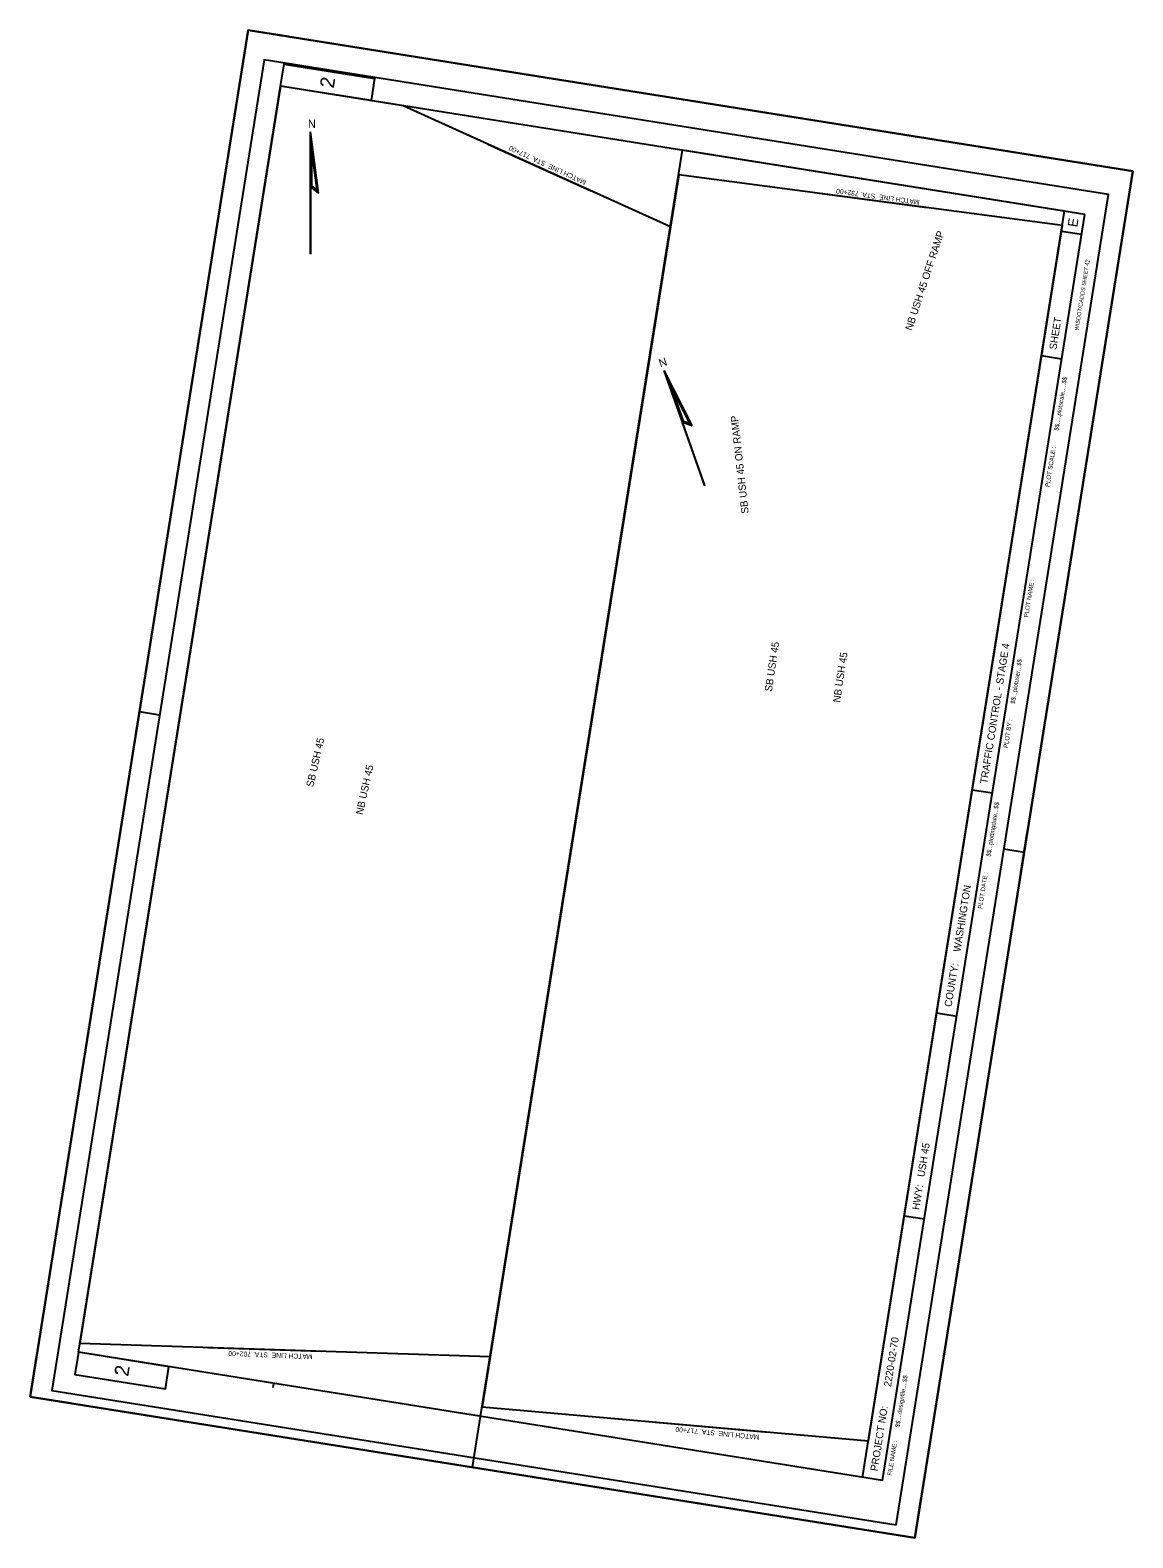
# Model space of a CAD drawing. Extents: x 354860 to 356215, y 192152 to 194004.
import ezdxf

# ---------------------------------------------------------------- set-up
doc = ezdxf.new("R2010")
doc.units = 0
for name, color, linetype in [('Default', 7, 'Continuous'), ('P_ALI_200_Equation', 7, 'Continuous'), ('P_ALI_200_PIData', 7, 'Continuous'), ('P_ALI_200_Sta', 7, 'Continuous'), ('P_ALI_20_PIData', 7, 'Continuous'), ('P_ALI_20_Tic', 7, 'Continuous'), ('P_ALI_50_Equation', 7, 'Continuous'), ('P_ALI_50_PIData', 7, 'Continuous'), ('P_ALI_50_Sta', 7, 'Continuous')]:
    doc.layers.add(name, color=color, linetype=linetype)

msp = doc.modelspace()

# ---------------------------------------------------------------- linework, layer by layer
at = {"layer": 'Default'}
for points in [[(354921.6, 192391.3), (355425.3, 192375.2), (355646.7, 193762.9), (355318.5, 193911.5), (355167.9, 193935.5)], [(354921.6, 192391.3), (355425.3, 192375.2), (355646.7, 193762.9), (355318.5, 193911.5), (355167.9, 193935.5)], [(354921.6, 192391.3), (355425.3, 192375.2), (355646.7, 193762.9), (355318.5, 193911.5), (355167.9, 193935.5)], [(355415.4, 192313.1), (355889.8, 192271.4), (356128, 193764.6), (355656.9, 193826.8)], [(355415.4, 192313.1), (355889.8, 192271.4), (356128, 193764.6), (355656.9, 193826.8)], [(355415.4, 192313.1), (355889.8, 192271.4), (356128, 193764.6), (355656.9, 193826.8)]]:
    msp.add_lwpolyline(points, close=True, dxfattribs=at)
at = {"layer": 'P_ALI_200_Equation'}
for points in [[(355946.7, 192152.3), (356214.5, 193831.1), (355128.3, 194004.4), (354860.4, 192325.6)], [(355923.9, 192168.1), (356184.6, 193802.4), (355147.7, 193967.9), (354887, 192333.5)]]:
    msp.add_lwpolyline(points, close=True, dxfattribs=at)
at = {"layer": 'P_ALI_200_PIData'}
for p, q in [((355120.4, 193955), (355128.3, 194004.4)), ((355177.6, 193996.5), (355128.3, 194004.4)), ((354919.8, 192380.2), (355167.9, 193935.5)), ((356155.4, 193778), (355167.9, 193935.5)), ((355413.5, 192301.4), (355661.7, 193856.8)), ((356214.5, 193831.1), (356165.1, 193839)), ((356206.6, 193781.7), (356214.5, 193831.1)), ((355882.6, 192226.6), (356130.7, 193781.9)), ((355907.3, 192222.7), (356155.4, 193778)), ((356151.5, 193753.3), (356126.8, 193757.2)), ((356127.1, 193600.2), (356102.4, 193604.2)), ((354990.8, 193142.8), (354998.7, 193192.1)), ((354994.7, 193167.5), (355019.4, 193163.5)), ((356042, 193067), (356017.3, 193070.9)), ((356077.1, 192969.5), (356084.9, 193018.8)), ((356081, 192994.2), (356056.3, 192998.1)), ((355998.3, 192792.9), (355973.6, 192796.9)), ((355958.5, 192543.6), (355933.8, 192547.5)), ((354860.4, 192325.6), (354868.3, 192375)), ((355907.3, 192222.7), (354919.8, 192380.2)), ((355159.3, 192342), (355158.5, 192337.1)), ((355419.4, 192338.5), (355419.4, 192338.5)), ((354909.8, 192317.7), (354860.4, 192325.6)), ((355403.6, 192239), (355413.5, 192301.4)), ((355428.3, 192235), (355378.9, 192242.9)), ((355946.7, 192152.3), (355954.6, 192201.7)), ((355946.7, 192152.3), (355897.3, 192160.2))]:
    msp.add_line(p, q, dxfattribs=at)
for points in [[(355167.9, 193935.5), (355172.2, 193962.7), (355283.3, 193945), (355279, 193917.8)], [(354919.8, 192380.2), (354915.4, 192353), (355026.5, 192335.3), (355030.9, 192362.5)]]:
    msp.add_lwpolyline(points, close=True, dxfattribs=at)
at = {"layer": 'P_ALI_200_Sta'}
msp.add_lwpolyline([(354860.4, 192325.6), (355128.3, 194004.4), (356214.5, 193831.1), (355946.7, 192152.3), (354860.4, 192325.6)], dxfattribs=at)
at = {"layer": 'P_ALI_20_PIData'}
for p, q in [((355214.7, 193804.3), (355204.7, 193879.3)), ((355204.7, 193811.8), (355204.7, 193879.3)), ((355205.5, 193812.2), (355205.5, 193868)), ((355213.7, 193806), (355205.5, 193868)), ((355206.2, 193812.6), (355206.2, 193856.7)), ((355212.7, 193807.7), (355206.2, 193856.7)), ((355204.7, 193811.8), (355214.7, 193804.3)), ((355204.7, 193729.3), (355204.7, 193811.8)), ((355205, 193729.3), (355205, 193811.6)), ((355205.5, 193812.2), (355213.7, 193806)), ((355206.2, 193812.6), (355212.7, 193807.7)), ((355673.4, 193518.9), (355639.1, 193586.4)), ((355661.4, 193522.7), (355639.1, 193586.4)), ((355662, 193523.3), (355643.5, 193575.9)), ((355671.9, 193520.2), (355643.5, 193575.9)), ((355662.6, 193523.9), (355648, 193565.5)), ((355670.4, 193521.4), (355648, 193565.5)), ((355661.4, 193522.7), (355673.4, 193518.9)), ((355688.8, 193444.8), (355661.4, 193522.7)), ((355689, 193444.9), (355661.7, 193522.6)), ((355662, 193523.3), (355671.9, 193520.2)), ((355662.6, 193523.9), (355670.4, 193521.4))]:
    msp.add_line(p, q, dxfattribs=at)
for points in [[(355204.7, 193879.3), (355204.7, 193879.3)], [(355639.1, 193586.3), (355639.1, 193586.3)]]:
    msp.add_lwpolyline(points, dxfattribs=at)
at = {"layer": 'P_ALI_20_Tic'}
for p, q in [((355422.5, 193864.4), (355549.4, 193806.9)), ((355823.8, 193804.8), (355962, 193786.5)), ((355078.7, 192386.3), (355218, 192381.8)), ((355628.2, 192294.4), (355767, 192282.2))]:
    msp.add_line(p, q, dxfattribs=at)
at = {"layer": 'P_ALI_50_PIData'}
msp.add_lwpolyline([(354860.4, 192325.6), (355128.3, 194004.4), (356214.5, 193831.1), (355946.7, 192152.3)], close=True, dxfattribs=at)
at = {"layer": 'P_ALI_50_Sta'}
msp.add_lwpolyline([(356130.7, 193781.9), (355661.7, 193856.8)], dxfattribs=at)

# ---------------------------------------------------------------- texts
at = {"layer": 'P_ALI_200_PIData'}
for s, height, rotation, p in [('2', 17.5, 80.9358, (355233.2, 193932.4)), ('E', 12, 80.9358, (356146.2, 193761.8)), ('WISDOT/CADDS SHEET 42', 5, 80.9358, (356147.8, 193635.1)), ('SHEET ', 9, 80.9358, (356120.7, 193611.4)), ('$$.....plotscale.....$$', 5.4, 80.9358, (356123.2, 193512.2)), ('PLOT SCALE : ', 5.4, 80.9358, (356112.1, 193442.9)), ('PLOT NAME :                      ', 5.4, 80.9358, (356086, 193282.7)), ('TRAFFIC CONTROL - STAGE 4', 9, 80.9358, (356035.7, 193078.1)), ('$$...plotuser...$$', 5.4, 80.9357, (356069.6, 193176.5)), ('PLOT BY :', 5.4, 80.9357, (356060.9, 193122.2)), ('$$...plottingdate...$$', 5.4, 80.9357, (356039.7, 192988.9)), ('PLOT DATE :', 5.4, 80.9357, (356029.4, 192924.7)), (' WASHINGTON', 9, 80.9358, (356002.2, 192868.3)), ('COUNTY:', 9, 80.9358, (355991.9, 192804.1)), (' USH 45', 9, 80.9358, (355958.1, 192591.8)), ('HWY:', 9, 80.9358, (355952.2, 192554.7)), (' 2220-02-70', 9, 80.9358, (355917, 192334)), ('2', 17.5, 80.9358, (354980.8, 192349.9)), ('$$....designfile....$$', 5.4, 80.9357, (355927.8, 192287.7)), ('PROJECT NO:', 9, 80.9358, (355901, 192233.8)), ('FILE NAME :', 5.4, 80.9358, (355918.3, 192228.5))]:
    msp.add_text(s, height=height, rotation=rotation, dxfattribs=at).set_placement(p)
at = {"layer": 'P_ALI_20_PIData'}
msp.add_text('N', height=10, dxfattribs=at).set_placement((355201.6, 193884.3))
msp.add_text('N', height=10, rotation=19.3422, dxfattribs=at).set_placement((355634.5, 193590))
at = {"layer": 'P_ALI_50_Equation'}
for s, height, rotation, p in [('MATCH LINE  STA. 717+00', 6, 155.2305, (355543.9, 193819.5)), ('MATCH LINE  STA. 732+00', 6, 172.0683, (355953, 193795.6)), ('NB USH 45 OFF RAMP', 9, 71.7093, (355943.1, 193634.7)), ('SB USH 45 ON RAMP', 9, 96.3025, (355742.8, 193411.1)), ('SB USH 45', 9, 81.4626, (355771.2, 193191.4)), ('NB USH 45', 9, 81.4626, (355855, 193178)), ('SB USH 45', 9, 77.2173, (355208.1, 193074)), ('NB USH 45', 9, 77.5935, (355268.8, 193040)), ('MATCH LINE  STA. 702+00', 6, 177.7583, (355207.3, 192377.8)), ('MATCH LINE  STA. 717+00', 6, 174.5728, (355756.1, 192278.8))]:
    msp.add_text(s, height=height, rotation=rotation, dxfattribs=at).set_placement(p)

doc.saveas('drawing.dxf')
